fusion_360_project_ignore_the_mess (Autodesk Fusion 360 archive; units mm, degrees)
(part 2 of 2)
sketch "Sketch29" plane through (0, 7.05, 0) normal (0, 1, 0) x axis (-1, 0, 0)
  line L1 (4.25, 43.8) -> (4.25, -2.05)
  line L2 (-29.7, 47.8) -> (0.25, 47.8)
  line L3 (-33.7, -2.05) -> (-33.7, 43.8)
  line L4 (0.25, -6.05) -> (-29.7, -6.05)
  line L5 (-8.5712, 33.45) -> (1.1, 33.45)
  line L6 (-30.9, 37.5538) -> (-30.9, 33.45)
  line L7 (1.1, 33.45) -> (1.1, 37.5538)
  line L8 (-30.9, 33.45) -> (-20.9, 33.45)
  line L9 (-3.1965, 41.45) -> (-23.0171, 41.45)
  line L10 (-30.9, -3.25) -> (1.1, -3.25)
  line L11 (-30.9, 19.45) -> (-30.9, -3.25)
  line L12 (1.1, -3.25) -> (1.1, 19.45)
  line L13 (-2.9, 3.35) -> (-26.9, 3.35)
  line L14 (-2.9, 2.15) -> (-2.9, 3.35)
  line L15 (-26.9, 2.15) -> (-2.9, 2.15)
  line L16 (-26.9, 3.35) -> (-26.9, 2.15)
  line L17 (-2.9, 1.15) -> (-26.9, 1.15)
  line L18 (-2.9, -0.05) -> (-2.9, 1.15)
  line L19 (-26.9, -0.05) -> (-2.9, -0.05)
  line L20 (-26.9, 1.15) -> (-26.9, -0.05)
  line L21 (-2.9, -1.05) -> (-26.9, -1.05)
  line L22 (-2.9, -2.25) -> (-2.9, -1.05)
  line L23 (-26.9, -2.25) -> (-2.9, -2.25)
  line L24 (-26.9, -1.05) -> (-26.9, -2.25)
  line L25 (-2.9, 4.35) -> (-26.9, 4.35)
  line L26 (-2.9, 5.55) -> (-2.9, 4.35)
  line L27 (-26.9, 5.55) -> (-2.9, 5.55)
  line L28 (-26.9, 4.35) -> (-26.9, 5.55)
  line L29 (-6.05, 40.45) -> (-23.75, 40.45)
  line L30 (-6.05, 39.25) -> (-6.05, 40.45)
  line L31 (-23.75, 39.25) -> (-6.05, 39.25)
  line L32 (-23.75, 40.45) -> (-23.75, 39.25)
  line L33 (-5.05, 38.25) -> (-24.75, 38.25)
  line L34 (-5.05, 37.05) -> (-5.05, 38.25)
  line L35 (-24.75, 37.05) -> (-5.05, 37.05)
  line L36 (-24.75, 38.25) -> (-24.75, 37.05)
  arc A1 centre (-14.725, 20.875) radius 9 clockwise from (-18.5821, 12.7434) to (-22.8566, 17.0179)
  arc A2 centre (-19.225, 11.3882) radius 1.5 clockwise from (-18.5821, 12.7434) to (-19.8679, 10.0329)
  arc A3 centre (-14.725, 20.875) radius 12 clockwise from (-19.8679, 10.0329) to (-25.5671, 15.7321)
  arc A4 centre (-24.2118, 16.375) radius 1.5 clockwise from (-25.5671, 15.7321) to (-22.8566, 17.0179)
  arc A5 centre (-14.725, 20.875) radius 9 clockwise from (-22.8566, 24.7321) to (-18.5821, 29.0066)
  arc A6 centre (-24.2118, 25.375) radius 1.5 clockwise from (-22.8566, 24.7321) to (-25.5671, 26.0179)
  arc A7 centre (-14.725, 20.875) radius 12 clockwise from (-25.5671, 26.0179) to (-19.8679, 31.7171)
  arc A8 centre (-19.225, 30.3618) radius 1.5 clockwise from (-19.8679, 31.7171) to (-18.5821, 29.0066)
  arc A9 centre (-14.725, 20.875) radius 9 clockwise from (-6.5934, 17.0179) to (-10.8679, 12.7434)
  arc A10 centre (-5.2382, 16.375) radius 1.5 clockwise from (-6.5934, 17.0179) to (-3.8829, 15.7321)
  arc A11 centre (-14.725, 20.875) radius 12 clockwise from (-3.8829, 15.7321) to (-9.5821, 10.0329)
  arc A12 centre (-10.225, 11.3882) radius 1.5 clockwise from (-9.5821, 10.0329) to (-10.8679, 12.7434)
  arc A13 centre (-14.725, 20.875) radius 9 clockwise from (-10.8679, 29.0066) to (-6.5934, 24.7321)
  arc A14 centre (-10.225, 30.3618) radius 1.5 clockwise from (-10.8679, 29.0066) to (-9.5821, 31.7171)
  arc A15 centre (-14.725, 20.875) radius 12 clockwise from (-9.5821, 31.7171) to (-3.8829, 26.0179)
  arc A16 centre (-5.2382, 25.375) radius 1.5 clockwise from (-3.8829, 26.0179) to (-6.5934, 24.7321)
  circle C1 centre (-14.725, 20.875) radius 3
  arc A17 centre (0.25, -2.05) radius 4 clockwise from (4.25, -2.05) to (0.25, -6.05)
  arc A18 centre (0.25, 43.8) radius 4 clockwise from (0.25, 47.8) to (4.25, 43.8)
  arc A19 centre (-29.7, 43.8) radius 4 clockwise from (-33.7, 43.8) to (-29.7, 47.8)
  arc A20 centre (-29.7, -2.05) radius 4 clockwise from (-29.7, -6.05) to (-33.7, -2.05)
  circle C2 centre (-14.725, 20.875) radius 15
  arc A21 centre (-28.75, 39.5) radius 2.9 clockwise from (-26.6035, 41.45) to (-30.9, 37.5538)
  arc A22 centre (-1.05, 39.5) radius 2.9 clockwise from (1.1, 37.5538) to (-3.1965, 41.45)
  point P55 (-26.9, 3.35)
  point P58 (-26.9, 2.15)
  point P59 (-26.9, 1.15)
  point P62 (-26.9, -0.05)
  point P63 (-26.9, -1.05)
  point P66 (-26.9, -2.25)
  point P67 (-26.9, 4.35)
  point P70 (-26.9, 5.55)
  point P71 (-23.75, 40.45)
  point P74 (-23.75, 39.25)
  point P75 (-24.75, 38.25)
  point P78 (-24.75, 37.05)
  point P48 (-1.05, 39.5)
  point P42 (-28.75, 39.5)
  horizontal L13
  vertical L14
  horizontal L15
  vertical L16
  horizontal L17
  vertical L18
  horizontal L19
  vertical L20
  horizontal L21
  vertical L22
  horizontal L23
  vertical L24
  horizontal L25
  vertical L26
  horizontal L27
  vertical L28
  collinear L18 L22
  collinear L14 L18
  collinear L14 L26
  collinear L20 L24
  collinear L16 L20
  collinear L16 L28
  horizontal L29
  vertical L30
  horizontal L31
  vertical L32
  horizontal L33
  vertical L34
  horizontal L35
  vertical L36
  dimension "d336" distance P55 P58 = 1.2
  dimension "d337" distance P59 P62 = 1.2
  dimension "d338" distance P63 P66 = 1.2
  dimension "d339" distance L10 L23 = 1
  dimension "d340" distance L19 L21 = 1
  dimension "d341" distance L15 L17 = 1
  dimension "d342" distance P67 P70 = 1.2
  dimension "d343" distance L13 L25 = 1
  dimension "d344" distance L11 L28 = 4
  dimension "d348" distance L12 L26 = 4
  dimension "d349" distance P71 P74 = 1.2
  dimension "d350" distance P75 P78 = 1.2
  dimension "d351" distance L9 L29 = 1
  dimension "d352" distance L31 L33 = 1
  dimension "d353" distance P48 L30 = 5
  dimension "d354" distance P42 L32 = 5
  dimension "d355" distance P48 L34 = 4
  dimension "d356" distance P42 L36 = 4
extrude "Extrude47" cut sketch "Sketch29" profile of L13 L14 L15 L16 L17 L18 L19 L20 L21 L22 L23 L24 L25 L26 L27 L28 L29 L30 L31 L32 L33 L34 L35 L36 to an object
fillet "Fillet11" radius 0.6 0.6
sketch "Sketch30" plane through (0, 0, 0) normal (0, 0, 1) x axis (1, 0, 0)
  curve K1 (28.9, 1.2926) -> (29.1741, 1.65)
  line L1 (24.5, 5.65) -> (30.5, 5.65)
  line L2 (24.5, -0.35) -> (24.5, 5.65)
  line L3 (30.5, -0.35) -> (24.5, -0.35)
  line L4 (30.5, 5.65) -> (30.5, -0.35)
  line L5 (24.5, -0.35) -> (30.5, 5.65)
  line L6 (30.5, -0.35) -> (24.5, 5.65)
  arc A1 centre (27.5, 2.65) radius 1.95 clockwise from (25.8259, 1.65) to (29.1741, 1.65)
  arc A2 centre (27.5, 2.65) radius 1.95 clockwise from (28.9, 1.2926) to (25.8259, 1.65)
  circle C1 centre (27.5, 2.65) radius 1.75
  point P14 (27.5, 2.65)
  point P4 (27.5, 2.65)
  point P12 (24.5, -0.35)
  point P13 (30.5, -0.35)
  point P11 (24.5, 5.65)
  concentric A2 C1
  horizontal L1
  perpendicular L1 L2
  parallel L1 L3
  parallel L2 L4
  coincident L5 P14
  coincident L6 P14
  coincident P4 P14
  dimension "d363" diameter C1 = 3.5
  dimension "d364" distance P12 P13 = 6
  dimension "d365" distance P11 P12 = 6
extrude "Extrude48" sketch "Sketch30" profile of C1 L1 L2 L3 L4 blind -3.5 from offset -0.2
extrude "Extrude49" sketch "Sketch30" profile of C1 blind 3
component_insert "Component Insert"
position "Position1"
position "Position2"
position "Position3"
sketch "Sketch31" plane through (0, 0, 0) normal (0, 1, 0) x axis (1, 0, 0)
  line L1 (2.2365, -40.85) -> (30.3, -40.85)
  line L2 (23.3, -39.45) -> (2.2365, -39.45)
  line L3 (23.3, -38.05) -> (2.2365, -38.05)
  line L4 (23.3, -18.6532) -> (2.225, -18.6532)
  line L5 (23.3, -17.2532) -> (2.225, -17.2532)
  line L6 (23.3, -15.8532) -> (2.225, -15.8532)
  line L7 (-0.9, 3.05) -> (30.7, 3.05)
  line L8 (30.7, 3.05) -> (30.7, -41.25)
  line L9 (30.7, -41.25) -> (-0.9, -41.25)
  line L10 (-0.9, -41.25) -> (-0.9, 3.05)
  line L11 (3.975, -19.4532) -> (3.7241, -19.4532)
  line L12 (3.975, -20.8532) -> (3.975, -19.4532)
  line L13 (3.075, -21.7032) -> (3.125, -21.7032)
  line L14 (2.225, -19.4532) -> (2.225, -20.8532)
  line L15 (2.4699, -19.4532) -> (2.225, -19.4532)
  line L16 (6.5288, -19.4532) -> (6.2799, -19.4532)
  line L17 (6.5288, -20.8532) -> (6.5288, -19.4532)
  line L18 (5.6288, -21.7032) -> (5.6788, -21.7032)
  line L19 (4.7788, -19.4532) -> (4.7788, -20.8532)
  line L20 (5.0257, -19.4532) -> (4.7788, -19.4532)
  line L21 (9.0826, -19.4532) -> (8.8357, -19.4532)
  line L22 (9.0826, -20.8532) -> (9.0826, -19.4532)
  line L23 (8.1826, -21.7032) -> (8.2326, -21.7032)
  line L24 (7.3326, -19.4532) -> (7.3326, -20.8532)
  line L25 (7.5816, -19.4532) -> (7.3326, -19.4532)
  line L26 (14.1903, -19.4532) -> (13.9474, -19.4532)
  line L27 (14.1903, -20.8532) -> (14.1903, -19.4532)
  line L28 (13.2903, -21.7032) -> (13.3403, -21.7032)
  line L29 (12.4403, -19.4532) -> (12.4403, -20.8532)
  line L30 (12.6932, -19.4532) -> (12.4403, -19.4532)
  line L31 (2.2365, -37.2532) -> (2.4774, -37.2532)
  line L32 (2.2365, -35.8532) -> (2.2365, -37.2532)
  line L33 (3.1365, -35.0032) -> (3.0865, -35.0032)
  line L34 (3.9865, -37.2532) -> (3.9865, -35.8532)
  line L35 (3.7315, -37.2532) -> (3.9865, -37.2532)
  line L36 (4.7903, -37.2532) -> (5.0332, -37.2532)
  line L37 (4.7903, -35.8532) -> (4.7903, -37.2532)
  line L38 (5.6903, -35.0032) -> (5.6403, -35.0032)
  line L39 (6.5403, -37.2532) -> (6.5403, -35.8532)
  line L40 (6.2874, -37.2532) -> (6.5403, -37.2532)
  line L41 (7.3441, -37.2532) -> (7.589, -37.2532)
  line L42 (7.3441, -35.8532) -> (7.3441, -37.2532)
  line L43 (8.2441, -35.0032) -> (8.1941, -35.0032)
  line L44 (9.0941, -37.2532) -> (9.0941, -35.8532)
  line L45 (8.8432, -37.2532) -> (9.0941, -37.2532)
  line L46 (12.4518, -37.2532) -> (12.7007, -37.2532)
  line L47 (12.4518, -35.8532) -> (12.4518, -37.2532)
  line L48 (13.3518, -35.0032) -> (13.3018, -35.0032)
  line L49 (14.2018, -37.2532) -> (14.2018, -35.8532)
  line L50 (13.9548, -37.2532) -> (14.2018, -37.2532)
  line L51 (2.2365, -40.85) -> (2.2365, -38.05)
  line L52 (0.6, 2.65) -> (28.8, 2.65)
  line L53 (0.6, 0.15) -> (0.6, 2.65)
  line L54 (28.8, 0.15) -> (0.6, 0.15)
  line L55 (28.8, 2.65) -> (28.8, 0.15)
  line L56 (21.8, -19.45) -> (21.8, -37.25)
  line L57 (19.0595, -19.45) -> (21.8, -19.45)
  line L58 (21.8, -37.25) -> (19.066, -37.25)
  line L59 (20.5, -14.4532) -> (2.225, -14.4532)
  line L60 (2.225, -18.6532) -> (2.225, -14.4532)
  line L61 (30.3, -5.85) -> (30.3, -40.85)
  line L62 (27.5, -5.85) -> (27.5, -35.25)
  line L63 (23.3, -11.6532) -> (23.3, -5.85)
  line L64 (24.7, -11.6532) -> (24.7, -5.85)
  line L65 (26.1, -21.4532) -> (26.1, -35.25)
  line L66 (30.3, -5.85) -> (23.3, -5.85)
  line L67 (26.1, -21.4532) -> (26.1, -17.6532)
  line L68 (26.1, -16.6035) -> (26.1, -17.6532)
  line L69 (26.1, -5.85) -> (26.1, -11.6532)
  line L70 (26.1, -11.6532) -> (26.1, -16.6035)
  line L71 (22, -19.25) -> (1.425, -19.25)
  line L72 (22, -37.45) -> (22, -19.25)
  line L73 (1.4365, -37.45) -> (22, -37.45)
  line L74 (28.9, -40.5897) -> (28.9, -40.85)
  line L75 (28.9, -5.85) -> (28.9, -35.25)
  line L76 (28.9, -35.25) -> (28.9, -38.4103)
  line L77 (28.9, -38.4103) -> (28.9, -40.5897)
  line L78 (30.7, -5.85) -> (30.3, -5.85)
  line L79 (20.5, -13.6532) -> (1.425, -13.6532)
  line L80 (22.5, -11.6532) -> (22.5, -5.85)
  line L81 (22.5, -5.85) -> (23.3, -5.85)
  line L82 (1.425, -13.6532) -> (1.425, -19.25)
  line L83 (1.4365, -41.25) -> (1.4365, -37.45)
  line L84 (22.8, -19.4532) -> (23.3, -19.4532)
  line L85 (22.8, -37.25) -> (23.3, -37.25)
  line L86 (25.3, -28.35) -> (22.8, -28.35)
  line L87 (22.8, -24.35) -> (25.3, -24.35)
  line L88 (22.8, -23.55) -> (25.3, -23.55)
  line L89 (22.8, -32.35) -> (25.3, -32.35)
  line L90 (22.8, -33.15) -> (25.3, -33.15)
  line L91 (22.8, -33.15) -> (22.8, -37.25)
  line L92 (25.3, -33.15) -> (25.3, -35.25)
  line L93 (22.8, -24.35) -> (22.8, -32.35)
  line L94 (22.8, -19.4532) -> (22.8, -23.55)
  line L95 (25.3, -24.35) -> (25.3, -32.35)
  line L96 (25.3, -21.4532) -> (25.3, -23.55)
  line L97 (22, -28.35) -> (22.8, -28.35)
  line L98 (-0.9, -5.85) -> (22.5, -5.85)
  line L99 (14.9941, -18.6532) -> (14.9941, -19.25)
  line L100 (14.9941, -20.8532) -> (14.9941, -19.4532)
  line L101 (15.0056, -38.05) -> (15.0056, -37.45)
  line L102 (15.0056, -37.2532) -> (15.0056, -35.8532)
  line L103 (20.5, -12.8532) -> (1.3, -12.8532)
  line L104 (21.7, -11.6532) -> (21.7, -5.85)
  line L105 (0.1, -6.85) -> (21.7, -6.85)
  line L106 (0.1, -11.6532) -> (0.1, -6.85)
  line L107 (10.9, -12.8532) -> (10.9, -6.85)
  line L108 (9.9, -6.85) -> (9.9, -12.8532)
  line L109 (11.9, -6.85) -> (11.9, -12.8532)
  circle C1 centre (1.05, -39.5) radius 1.1
  circle C2 centre (28.75, -39.5) radius 1.1
  arc A1 centre (3.097, -19.3532) radius 0.635 clockwise from (3.7241, -19.4532) to (2.4699, -19.4532)
  arc A2 centre (3.125, -20.8532) radius 0.85 clockwise from (3.975, -20.8532) to (3.125, -21.7032)
  arc A3 centre (3.075, -20.8532) radius 0.85 clockwise from (3.075, -21.7032) to (2.225, -20.8532)
  circle C3 centre (3.097, -20.8532) radius 0.635
  arc A4 centre (5.6528, -19.3532) radius 0.635 clockwise from (6.2799, -19.4532) to (5.0257, -19.4532)
  arc A5 centre (5.6788, -20.8532) radius 0.85 clockwise from (6.5288, -20.8532) to (5.6788, -21.7032)
  arc A6 centre (5.6288, -20.8532) radius 0.85 clockwise from (5.6288, -21.7032) to (4.7788, -20.8532)
  circle C4 centre (5.6528, -20.8532) radius 0.635
  arc A7 centre (8.2086, -19.3532) radius 0.635 clockwise from (8.8357, -19.4532) to (7.5816, -19.4532)
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  point P4 (2.2365, -39.45)
  point P7 (2.225, -17.2532)
  point P8 (2.225, -15.8532)
  point P122 (28.9, -40.85)
  point P143 (28.9, -5.85)
  point P144 (27.5, -5.85)
  point P145 (26.1, -5.85)
  point P146 (24.7, -5.85)
  point P166 (28.9, -38.4103)
  point P167 (28.9, -40.5897)
  point P168 (30.7, -5.85)
  point P174 (1.4365, -41.25)
  point P185 (25.3, -24.35)
  point P186 (22.8, -24.35)
  point P187 (25.3, -23.55)
  point P188 (22.8, -23.55)
  point P189 (25.3, -32.35)
  point P190 (22.8, -32.35)
  point P191 (25.3, -33.15)
  point P192 (22.8, -33.15)
  point P183 (22.8, -28.35)
  point P184 (25.3, -28.35)
  point P193 (22, -28.35)
  point P194 (-0.9, -5.85)
  point P195 (14.9941, -19.25)
  point P196 (14.9941, -18.6532)
  point P199 (15.0056, -37.45)
  point P200 (15.0056, -38.05)
  point P208 (21.7, -6.85)
  point P212 (10.9, -6.85)
  point P213 (10.9, -12.8532)
  point P214 (9.9, -12.8532)
  point P215 (9.9, -6.85)
  point P216 (11.9, -12.8532)
  point P217 (11.9, -6.85)
  point P218 (9.9, -11.6532)
  point P219 (8.7, -12.8532)
  point P221 (9.9, -11.6532)
  point P220 (8.7, -12.8532)
  point P224 (13.1, -12.8532)
  point P225 (11.9, -11.6532)
  point P114 (28.8, 0.15)
  point P142 (30.3, -5.85)
  point P139 (26.1, -11.6532)
  point P159 (26.1, -16.6035)
  point P203 (1.3, -12.8532)
  point P210 (0.1, -11.6532)
  horizontal L1
  horizontal L2
  horizontal L3
  horizontal L4
  horizontal L5
  horizontal L6
  coincident P4 L51
  perpendicular L3 L51
  collinear L32 L51
  horizontal L59
  perpendicular L4 L60
  coincident P7 L60
  coincident P8 L60
  collinear L14 L60
  parallel L8 L61
  perpendicular L3 L68
  coincident L1 P122
  perpendicular L1 L74
  perpendicular L2 L62
  parallel L64 L68
  vertical L63
  perpendicular L3 L65
  perpendicular L8 L66
  coincident L66 P143
  coincident L66 P144
  coincident L66 P145
  coincident L66 P146
  collinear L65 L67
  perpendicular L66 L69
  perpendicular L56 L71
  perpendicular L57 L72
  perpendicular L72 L73
  coincident C2 P166
  coincident C2 P167
  perpendicular L1 L77
  coincident L8 P168
  perpendicular L8 L78
  perpendicular L63 L81
  perpendicular L71 L82
  coincident L9 P174
  perpendicular L9 L83
  vertical L91
  perpendicular L84 L91
  perpendicular L85 L91
  perpendicular L86 L92
  coincident P185 L92
  coincident P186 L91
  perpendicular L87 L91
  coincident P187 L92
  coincident P188 L91
  perpendicular L88 L91
  symmetric L86 P185 P189
  symmetric L86 P186 P190
  symmetric L86 P187 P191
  symmetric L86 P188 P192
  collinear L91 L93
  coincident P183 L91
  collinear L92 L95
  coincident P184 L92
  collinear L93 L94
  collinear L95 L96
  midpoint L72 P193
  perpendicular L93 L97
  perpendicular L80 L98
  coincident L10 P194
  coincident L71 P195
  coincident L4 P196
  perpendicular L4 L99
  collinear L99 L100
  coincident L73 P199
  coincident L3 P200
  perpendicular L3 L101
  collinear L101 L102
  coincident L104 P208
  perpendicular L104 L105
  perpendicular L105 L106
  midpoint L105 P212
  coincident L103 P213
  perpendicular L103 L107
  coincident L103 P214
  coincident L105 P215
  perpendicular L105 L108
  coincident L103 P216
  coincident L105 P217
  perpendicular L105 L109
  coincident L108 P218
  coincident L103 P219
  coincident P218 P221
  coincident P219 P220
  symmetric L107 P220 P224
  symmetric L107 P221 P225
  dimension "d372" distance L1 L2 = 1.4
  dimension "d373" distance L2 L3 = 1.4
  dimension "d376" distance L4 L5 = 1.4
  dimension "d377" distance L5 L6 = 1.4
  dimension "d380" distance L1 L9 = 0.4
  dimension "d381" distance L4 L11 = 0.8
  dimension "d382" distance L6 L59 = 1.4
  dimension "d383" distance L8 L61 = 0.4
  dimension "d386" distance L61 L74 = 1.4
  dimension "d388" distance L62 L74 = 1.4
  dimension "d389" radius = 2.8 (= "( 1.4 * 2 ) * 1 mm")
  dimension "d390" radius = 4.2 (= "( 1.4 * 2 ) * 1 mm + 1.4 mm")
  dimension "d391" = 1.4
  dimension "d401" radius = 2.8
  dimension "d402" = 1.4
  dimension "d404" distance L63 L64 = 1.4
  dimension "d405" distance L64 L68 = 1.4
  dimension "d407" distance P114 P142 = 6
  dimension "d408" radius = 2.8
  dimension "d409" distance L62 L68 = 1.4
  dimension "d410" = 1.4
  dimension "d412" radius = 5.6
  dimension "d413" distance P139 P159 = 4.9503
  dimension "d414" distance L58 L73 = 0.2
  dimension "d415" distance L56 L72 = 0.2
  dimension "d416" distance L57 L71 = 0.2
  dimension "d417" distance L61 L75 = 1.4
  dimension "d418" = 0.8
  dimension "d419" distance L60 L82 = 0.8
  dimension "d420" distance L51 L83 = 0.8
  dimension "d422" distance L72 L91 = 0.8
  dimension "d423" distance L87 L88 = 0.8
  dimension "d424" distance L86 L87 = 4
  dimension "d467" = 0.8
  dimension "d468" distance L98 L105 = 1
  dimension "d469" distance L10 L106 = 1
  dimension "d470" distance P203 P210 = 1.2
  dimension "d471" distance L107 L109 = 1
  dimension "d472" distance L107 L108 = 1
  dimension "d473" distance L103 P218 = 1.2
  dimension "d474" distance P214 P219 = 1.2
extrude "Extrude50" sketch "Sketch31" to an object offset -0.2 from offset 0.2
extrude "Extrude51" sketch "Sketch31" blind -3.4 (= "( -1.4 * 2 ) * 1 mm - 0.6 mm")
extrude "Extrude52" sketch "Sketch31" to an object offset 0.4
chamfer "Chamfer21" distance 1 distance 1.5
extrude "Extrude53" cut of existing geometry to an object
fillet "Fillet12" radius 4.2 (= "( 1.4 * 3 ) * 1 mm")
chamfer "Chamfer22" distance 2.4 distance 5.6
fillet "Fillet13" radius 1.8
shell "Shell1" innerThickness 1
extrude "Extrude54" add of existing geometry to an object
extrude "Extrude55" add of existing geometry to an object
sketch "Sketch32" plane through (0, 0, 0) normal (0, 0, 1) x axis (1, 0, 0)
  line L1 (30.3, 8.85) -> (30.3, 5.45)
  line L2 (30.7, 8.85) -> (30.3, 8.85)
  line L3 (30.7, 1.85) -> (30.7, 8.85)
  line L4 (-0.9, 1.85) -> (30.7, 1.85)
  line L5 (-0.9, 8.85) -> (-0.9, 1.85)
  line L6 (23.3, 8.85) -> (-0.9, 8.85)
  line L7 (23.3, 5.45) -> (23.3, 8.85)
  line L8 (30.3, 5.45) -> (23.3, 5.45)
  line L9 (29.7, 3.25) -> (29.7, 1.85)
  line L10 (0.1, 3.25) -> (29.7, 3.25)
  line L11 (0.1, 1.85) -> (0.1, 3.25)
  point P10 (29.7, 1.85)
  point P13 (0.1, 1.85)
  coincident L4 P10
  perpendicular L4 L9
  perpendicular L5 L10
  coincident L4 P13
  perpendicular L4 L11
  dimension "d450" distance L5 L11 = 1
  dimension "d451" distance L3 L9 = 1
  dimension "d452" distance L4 L10 = 1.4
extrude "Extrude56" sketch "Sketch32" profile of L4 L9 L10 L11 to an object
extrude "Extrude57" new body of existing geometry to an object from offset 0.2
extrude "Extrude58" cut of existing geometry to an object
sketch "Sketch33" plane through (0, 0, 0) normal (0, 1, 0) x axis (1, 0, 0)
  line L1 (0.1, -40.25) -> (0.1, -5.85)
  line L2 (29.7, -40.25) -> (0.1, -40.25)
  line L3 (29.7, -5.85) -> (29.7, -40.25)
  line L4 (30.7, -5.85) -> (29.7, -5.85)
  line L5 (30.7, -41.25) -> (30.7, -5.85)
  line L6 (-0.9, -41.25) -> (30.7, -41.25)
  line L7 (-0.9, -5.85) -> (-0.9, -41.25)
  line L8 (0.1, -5.85) -> (-0.9, -5.85)
  line L9 (29.7, -35.2805) -> (29.7, -6.85)
  line L10 (27.9, -35.2805) -> (29.7, -35.2805)
  line L11 (27.9, -37.05) -> (27.9, -35.2805)
  line L12 (0.1, -40.25) -> (24.7, -40.25)
  line L13 (0.1, -37.05) -> (0.1, -40.25)
  line L14 (23.3, -37.05) -> (0.1, -37.05)
  line L15 (25.1, -21.4532) -> (25.1, -35.25)
  line L16 (0.1, -19.6532) -> (23.3, -19.6532)
  line L17 (0.1, -13.4532) -> (0.1, -19.6532)
  line L18 (20.5, -13.4532) -> (0.1, -13.4532)
  line L19 (22.3, -6.85) -> (22.3, -11.6532)
  line L20 (29.7, -6.85) -> (22.3, -6.85)
  line L21 (29.7, -40.25) -> (29.7, -35.5957)
  line L22 (24.7, -40.25) -> (29.7, -40.25)
  line L23 (27.9, -35.5957) -> (27.9, -37.05)
  line L24 (29.7, -35.5957) -> (27.9, -35.5957)
  line L25 (29.7, -35.5957) -> (29.7, -35.2805)
  line L26 (27.9, -35.5957) -> (29.7, -35.5957)
  line L27 (27.9, -35.2805) -> (27.9, -35.5957)
  line L28 (29.7, -35.2805) -> (27.9, -35.2805)
  line L29 (27.85, -39.5) -> (28.75, -39.5)
  line L30 (28.75, -38.6) -> (28.75, -39.5)
  line L31 (29.7, -38.6) -> (28.75, -38.6)
  line L32 (27.85, -40.25) -> (27.85, -39.5)
  line L33 (1.95, -39.5) -> (1.05, -39.5)
  line L34 (1.05, -38.6) -> (1.05, -39.5)
  line L35 (0.1, -38.6) -> (1.05, -38.6)
  line L36 (1.95, -40.25) -> (1.95, -39.5)
  circle C1 centre (1.05, -39.5) radius 0.9
  arc A1 centre (24.7, -37.05) radius 3.2 clockwise from (27.9, -37.05) to (24.7, -40.25)
  arc A2 centre (23.3, -35.25) radius 1.8 clockwise from (25.1, -35.25) to (23.3, -37.05)
  arc A3 centre (23.3, -21.4532) radius 1.8 clockwise from (23.3, -19.6532) to (25.1, -21.4532)
  arc A4 centre (20.5, -11.6532) radius 1.8 clockwise from (22.3, -11.6532) to (20.5, -13.4532)
  arc A5 centre (24.7, -37.05) radius 3.2 clockwise from (27.9, -37.05) to (24.7, -40.25)
  circle C2 centre (28.75, -39.5) radius 0.9
  point P41 (28.75, -39.5)
  point P42 (28.75, -39.5)
  point P43 (27.85, -39.5)
  point P44 (28.75, -39.5)
  point P45 (28.75, -38.6)
  point P46 (29.7, -38.6)
  point P47 (27.85, -40.25)
  point P2 (1.05, -39.5)
  point P48 (1.05, -39.5)
  point P49 (1.95, -39.5)
  point P50 (1.05, -38.6)
  point P51 (0.1, -38.6)
  point P52 (1.95, -40.25)
  coincident P41 P42
  coincident C2 P43
  horizontal L29
  coincident P41 P44
  coincident C2 P45
  perpendicular L29 L30
  coincident L21 P46
  perpendicular L3 L31
  coincident L22 P47
  perpendicular L2 L32
  coincident P2 P48
  coincident C1 P49
  horizontal L33
  coincident C1 P50
  perpendicular L33 L34
  coincident L1 P51
  coincident L12 P52
  perpendicular L12 L36
  perpendicular L13 L35
extrude "Extrude59" sketch "Sketch33" profile of C1 L1 L2 L12 L13 L35 L36 to an object
extrude "Extrude60" sketch "Sketch33" profile of L2 L3 L21 L22 C2 L31 L32 to an object
extrude "Extrude61" sketch "Sketch31" to an object
extrude "Extrude62" cut of existing geometry to an object
offset_faces "OffsetFaces27" distance -0.2
offset_faces "OffsetFaces28" distance -0.2
delete_face "DeleteFace20"
delete_face "DeleteFace21"
delete_face "DeleteFace22"
delete_face "DeleteFace23"
delete_face "DeleteFace24"
delete_face "DeleteFace25"
delete_face "DeleteFace26"
delete_face "DeleteFace27"
delete_face "DeleteFace28"
delete_face "DeleteFace29"
delete_face "DeleteFace30"
delete_face "DeleteFace31"
split "Split2" bodies "case_back (1)"
combine "Combine10"
extrude "Extrude63" add of existing geometry to an object offset 1
move "Move16"
move "Move17"
combine "Combine11" bodies "case_back (1)"
sketch "Sketch34" plane through (0, 0, 0) normal (0, 0, 1) x axis (1, 0, 0)
  curve K1 (28.9, 1.2926) -> (29.1741, 1.65)
  line L1 (29.45, 2.65) -> (27.5, 2.65)
  line L2 (25.55, 2.65) -> (27.5, 2.65)
  line L3 (0.55, 0.25) -> (28.9, 0.25)
  line L4 (28.9, 0.25) -> (30.6436, 0.25)
  line L5 (29.45, 0.25) -> (29.45, 2.65)
  line L6 (25.55, 0.25) -> (25.55, 2.65)
  arc A1 centre (27.5, 2.65) radius 1.95 clockwise from (25.8259, 1.65) to (29.1741, 1.65)
  arc A2 centre (27.5, 2.65) radius 1.95 clockwise from (28.9, 1.2926) to (25.8259, 1.65)
  point P4 (27.5, 2.65)
  point P9 (27.5, 2.65)
  point P10 (29.45, 2.65)
  point P11 (25.55, 2.65)
  point P15 (29.45, 0.25)
  point P16 (25.55, 0.25)
  coincident P4 P9
  coincident A1 P10
  horizontal L1
  coincident A1 P11
  parallel L1 L2
  coincident L4 P15
  tangent A1 L5
  coincident L3 P16
  tangent A1 L6
extrude "Extrude64" sketch "Sketch34" profile of A1 A2 K1 L3 L4 L5 L6 to an object
sketch "Sketch35" plane through (-4.25, 0, 0) normal (-1, 0, 0) x axis (0, -1, 0)
  line L1 (-15.15, 43.8) -> (-1.65, 43.8)
  line L2 (-15.15, -2.05) -> (-15.15, 43.8)
  line L3 (-1.65, -2.05) -> (-15.15, -2.05)
  line L4 (-1.65, 43.8) -> (-1.65, -2.05)
  line L5 (-9.95, 31.35) -> (-9.95, 25.35)
  line L6 (-11.65, 32.85) -> (-11.45, 32.85)
  line L7 (-13.15, 25.35) -> (-13.15, 31.35)
  line L8 (-11.45, 23.85) -> (-11.65, 23.85)
  line L9 (-11.45, 23.25) -> (-11.65, 23.25)
  line L10 (-9.35, 31.35) -> (-9.35, 25.35)
  line L11 (-11.65, 33.45) -> (-11.45, 33.45)
  line L12 (-13.75, 25.35) -> (-13.75, 31.35)
  line L13 (-11.45, 22.05) -> (-11.65, 22.05)
  line L14 (-8.15, 31.35) -> (-8.15, 25.35)
  line L15 (-11.65, 34.65) -> (-11.45, 34.65)
  line L16 (-14.95, 25.35) -> (-14.95, 31.35)
  arc A1 centre (-11.45, 25.35) radius 1.5 clockwise from (-9.95, 25.35) to (-11.45, 23.85)
  arc A2 centre (-11.45, 31.35) radius 1.5 clockwise from (-11.45, 32.85) to (-9.95, 31.35)
  arc A3 centre (-11.65, 31.35) radius 1.5 clockwise from (-13.15, 31.35) to (-11.65, 32.85)
  arc A4 centre (-11.65, 25.35) radius 1.5 clockwise from (-11.65, 23.85) to (-13.15, 25.35)
  arc A5 centre (-11.65, 25.35) radius 2.1 clockwise from (-11.65, 23.25) to (-13.75, 25.35)
  arc A6 centre (-11.45, 25.35) radius 2.1 clockwise from (-9.35, 25.35) to (-11.45, 23.25)
  arc A7 centre (-11.45, 31.35) radius 2.1 clockwise from (-11.45, 33.45) to (-9.35, 31.35)
  arc A8 centre (-11.65, 31.35) radius 2.1 clockwise from (-13.75, 31.35) to (-11.65, 33.45)
  arc A9 centre (-11.65, 25.35) radius 3.3 clockwise from (-11.65, 22.05) to (-14.95, 25.35)
  arc A10 centre (-11.45, 25.35) radius 3.3 clockwise from (-8.15, 25.35) to (-11.45, 22.05)
  arc A11 centre (-11.45, 31.35) radius 3.3 clockwise from (-11.45, 34.65) to (-8.15, 31.35)
  arc A12 centre (-11.65, 31.35) radius 3.3 clockwise from (-14.95, 31.35) to (-11.65, 34.65)
  dimension "d488" = 0.6
  dimension "d502" = 1.8
extrude "Extrude65" cut sketch "Sketch35" profile of L10 A5 A6 L9 A7 L11 A8 L12 against normal blind 4
sketch "Sketch36" plane through (0, 0, 0) normal (0, 1, 0) x axis (1, 0, 0)
  line L1 (-2.2, -31.35) -> (-2.2, -32.85)
  line L2 (5.2, -31.35) -> (-2.2, -31.35)
  line L3 (5.2, -32.85) -> (5.2, -31.35)
  line L4 (-2.2, -32.85) -> (5.2, -32.85)
  line L5 (5.2, -25.35) -> (-2.2, -25.35)
  line L6 (5.2, -31.35) -> (5.2, -25.35)
  line L7 (-2.2, -31.35) -> (5.2, -31.35)
  line L8 (-2.2, -25.35) -> (-2.2, -31.35)
  line L9 (5.2, -25.35) -> (5.2, -23.85)
  line L10 (-2.2, -25.35) -> (5.2, -25.35)
  line L11 (-2.2, -23.85) -> (-2.2, -25.35)
  line L12 (5.2, -23.85) -> (-2.2, -23.85)
  line L13 (5.5, -33.15) -> (-2.5, -33.15)
  line L14 (5.5, -23.55) -> (5.5, -33.15)
  line L15 (-2.5, -23.55) -> (5.5, -23.55)
  line L16 (-2.5, -33.15) -> (-2.5, -23.55)
  horizontal L13
  vertical L14
  horizontal L15
  vertical L16
  dimension "d491" distance L11 L16 = 0.3
  dimension "d492" distance L12 L15 = 0.3
  dimension "d493" distance L9 L14 = 0.3
  dimension "d494" distance L4 L13 = 0.3
extrude "Extrude66" sketch "Sketch36" profile of L13 L14 L15 L16 to an object
chamfer "Chamfer23" distance 0.8 distance 0.4
chamfer "Chamfer24" distance 0.8 distance 0.8
extrude "Extrude68" sketch "Sketch35" profile of L10 A5 A6 L9 A7 L11 A8 L12 L14 A9 A10 L13 A11 L15 A12 L16 to an object from offset 0.8
sketch "Sketch37" plane through (0, 0, 0) normal (0, 1, 0) x axis (1, 0, 0)
  circle C1 centre (7.8408, -25.6437) radius 0.85
  circle C2 centre (7.8408, -31.1437) radius 0.85
extrude "Extrude69" cut sketch "Sketch37" to an object
chamfer "Chamfer25" distance 1 distance 1
move "Move18"
extrude "Extrude67" cut sketch "Sketch35" profile of L10 A5 A6 L9 A7 L11 A8 L12 L14 A9 A10 L13 A11 L15 A12 L16 against normal blind 0.95 (magnitude of "-1.75 mm + 0.8 mm")
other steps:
base_feature "Base Feature1"
base_feature "Base Feature2"
base_feature "Base Feature3" bodies "brasinho", "brasinho 2"
named bodies: "screen", "case_front", "case_back", "mount", "clamp", "screw", "brasinho", "brasinho 2", "case_back (1)"

design "ESP32-C3 supermini v5"
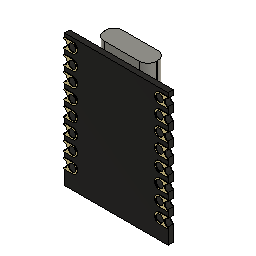
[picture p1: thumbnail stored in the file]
description: Part Number
part number: ESP32-C3 supermini
base_feature "Base Feature"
